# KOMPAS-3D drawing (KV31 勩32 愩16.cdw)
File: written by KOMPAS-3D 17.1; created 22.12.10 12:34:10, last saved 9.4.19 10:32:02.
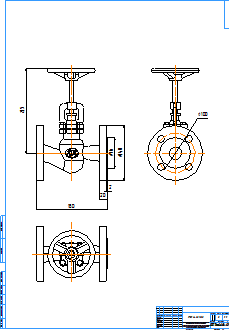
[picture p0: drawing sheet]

Title block, sheet 1: name: KV31 Ду32 Ру16; material: Внимание! Данный продукт является объектом авторского права ООО «Торговый Дом АДЛ». / Запрещается изменение, копирование, распространение / (в том числе путем копирования на другие сайты и ресурсы в Интернете) / или любое иное использование информации и объектов без предварительного / согласия правообладателя (ООО «Торговый Дом АДЛ»).; mass: 8; scale: 1:1; sheets: 1; organisation: ООО "Торговый дом АДЛ"; sheet format: A1; stored path: \\adlc.lan\data\АДЛ_ПКД\3D-модели\ADL production\Вентили ГРАНВЕНТ\KV31\KOMPAS 2D\KV31 Ду32.cdw

Views: Спереди 1, Проекционный вид 2, Вид 5
Dimensions and other numbers on the sheet: 76; 140; 2; 20; 180; 100; 215; 1:1; 1; 8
